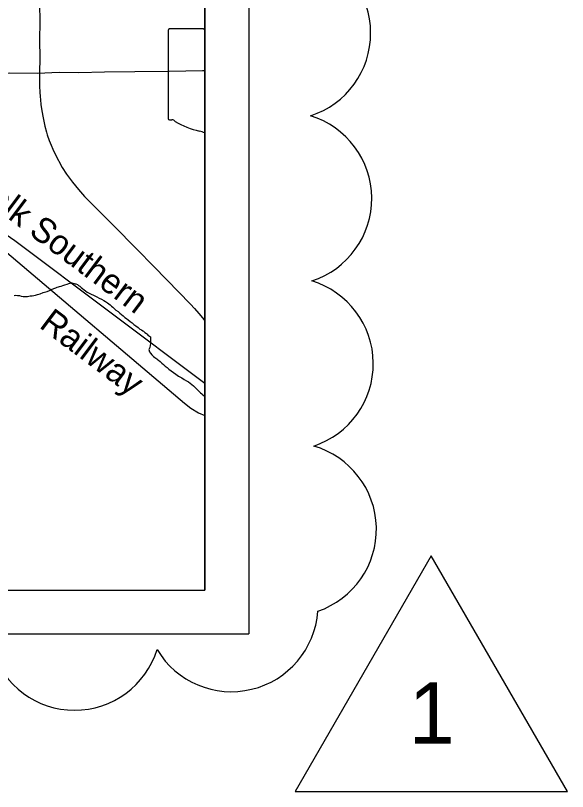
# Model space of a CAD drawing. Extents: x 0 to 96.2, y -27.5 to 31.3.
# Drawn here: x 50.194 to 51.448, y 13.529 to 15.293 of the extents above; entities that cross this region are included whole.
import ezdxf

# ---------------------------------------------------------------- set-up
doc = ezdxf.new("R2010")
doc.units = 0
for name, color, linetype in [('BOTTOM-BLKS', 7, 'Continuous'), ('TB1', 7, 'Continuous'), ('TB_BORDER', 7, 'Continuous'), ('TB_DUAL_PROF', 7, 'Continuous'), ('TB_PP_50x10_GRID', 7, 'Continuous'), ('TB_PROF_20x5', 7, 'Continuous'), ('TB_PSDSOD', 7, 'Continuous'), ('TB_SUPER_50x1_GRID', 7, 'Continuous')]:
    doc.layers.add(name, color=color, linetype=linetype)

msp = doc.modelspace()

# ---------------------------------------------------------------- linework, layer by layer
at = {"layer": 'BOTTOM-BLKS'}
msp.add_lwpolyline([(43.8234, 18.3711), (43.8234, 13.9869), (50.6234, 13.9869), (50.6234, 20.7869), (47.5697, 20.7869)], dxfattribs=at)
at = {"layer": 'TB1'}
for p, q in [((50.7234, 20.8869), (50.7234, 13.8869)), ((50.6234, 20.7869), (50.6234, 13.9869)), ((43.8234, 13.9869), (50.6234, 13.9869)), ((43.7234, 13.8869), (50.7234, 13.8869))]:
    msp.add_line(p, q, dxfattribs=at)
at = {"layer": 'TB_BORDER'}
for points in [[(50.1904, 14.6565), (50.1942, 14.6569), (50.1984, 14.6566), (50.203, 14.6563), (50.2068, 14.6552), (50.211, 14.6541), (50.2144, 14.6538), (50.2179, 14.6538), (50.2205, 14.6542), (50.2236, 14.6547), (50.227, 14.6555), (50.2311, 14.6559), (50.2349, 14.6564), (50.2387, 14.6568), (50.2437, 14.6584), (50.2497, 14.66), (50.2561, 14.6631), (50.2652, 14.6652), (50.2705, 14.6675), (50.2754, 14.6703), (50.2807, 14.6726), (50.2852, 14.6742), (50.2886, 14.675), (50.2913, 14.6758), (50.2939, 14.6766), (50.297, 14.6778), (50.3008, 14.679)], [(50.3008, 14.679), (50.3057, 14.6806), (50.311, 14.6822), (50.3147, 14.6838), (50.3174, 14.6846), (50.3212, 14.6854), (50.3288, 14.6829), (50.3307, 14.6829), (50.3346, 14.6814), (50.3369, 14.6795), (50.3396, 14.6773), (50.343, 14.6747), (50.3461, 14.6721), (50.3496, 14.6695), (50.3527, 14.6668), (50.3561, 14.6642), (50.3608, 14.6616), (50.3657, 14.6594), (50.3711, 14.6568), (50.378, 14.6531), (50.3838, 14.6506), (50.3891, 14.648), (50.3941, 14.645), (50.3983, 14.6424), (50.4026, 14.6398), (50.4056, 14.6376), (50.4087, 14.6349), (50.4118, 14.6323), (50.4145, 14.6297), (50.418, 14.6271), (50.4215, 14.623), (50.4265, 14.62), (50.4303, 14.6162), (50.4342, 14.6129), (50.4384, 14.6099), (50.4423, 14.6065), (50.4458, 14.6039), (50.4496, 14.6009), (50.4538, 14.5976), (50.4585, 14.5942), (50.4627, 14.5908), (50.4666, 14.5875), (50.472, 14.5834), (50.4762, 14.58), (50.4796, 14.5782), (50.4827, 14.5763), (50.4846, 14.5752), (50.4877, 14.5726), (50.4908, 14.5703), (50.4924, 14.5684), (50.4939, 14.5666), (50.4958, 14.5655), (50.5001, 14.5625), (50.5001, 14.5571), (50.5002, 14.5537), (50.5003, 14.5476), (50.4985, 14.5385), (50.4967, 14.5335), (50.498, 14.5286), (50.5003, 14.5252), (50.5034, 14.5214), (50.5069, 14.518), (50.5099, 14.5158), (50.5126, 14.514), (50.5146, 14.5128), (50.5165, 14.511), (50.5188, 14.5091), (50.5219, 14.5061), (50.5258, 14.5027), (50.53, 14.4994), (50.5339, 14.496), (50.5381, 14.493), (50.542, 14.4893), (50.5473, 14.4852), (50.5524, 14.4814), (50.5577, 14.4777), (50.5635, 14.4728), (50.5712, 14.4691), (50.5766, 14.4658), (50.5819, 14.4625), (50.5866, 14.4599), (50.5904, 14.4573), (50.5943, 14.4543), (50.5977, 14.4513), (50.607, 14.4419), (50.6097, 14.4389), (50.614, 14.4348), (50.6167, 14.4325), (50.6194, 14.4303), (50.6221, 14.428), (50.6234, 14.4271)], [(50.6234, 14.3358), (50.6232, 14.3348), (50.6229, 14.3329), (50.6233, 14.3276), (50.623, 14.3257), (50.6234, 14.3239)]]:
    msp.add_lwpolyline(points, dxfattribs=at)
at = {"layer": 'TB_DUAL_PROF'}
for p, q in [((50.5433, 15.2625), (50.5433, 15.2625)), ((50.6234, 15.0259), (50.6234, 15.2605)), ((50.5407, 15.0589), (50.5407, 15.0589))]:
    msp.add_line(p, q, dxfattribs=at)
for points in [[(50.5407, 15.2591), (50.5407, 15.2591), (50.5407, 15.0589)], [(50.6205, 15.2625), (50.6205, 15.2625), (50.5433, 15.2625)]]:
    msp.add_lwpolyline(points, dxfattribs=at)
for centre, radius, start, end in [((50.5437, 15.2595), 0.00305, 98.1301, 188.1301), ((50.6389, 15.2857), 0.0296, 231.6195, 238.3868), ((50.5437, 15.0585), 0.00308, 171.9584, 258.3066), ((50.5442, 15.079), 0.0235, 267.339, 280.6039), ((50.549, 15.0474), 0.00848, 29.7484, 93.2717), ((50.6561, 15.2272), 0.2019, 240.4129, 257.1985), ((50.5959, 14.969), 0.0632, 64.2129, 75.836)]:
    msp.add_arc(centre, radius, start, end, dxfattribs=at)
at = {"layer": 'TB_PP_50x10_GRID'}
for points in [[(50.2483, 15.32), (50.2485, 15.2779), (50.2484, 15.2382), (50.2485, 15.1953), (50.2482, 15.1639), (50.2484, 15.1323), (50.2488, 15.1188), (50.2494, 15.1091), (50.2502, 15.1009), (50.2514, 15.0908), (50.2528, 15.0807), (50.2555, 15.0644), (50.2605, 15.041), (50.2639, 15.0279), (50.2658, 15.0217), (50.2703, 15.0087), (50.2746, 14.9978), (50.2786, 14.9888), (50.2835, 14.9776), (50.2999, 14.9476), (50.3096, 14.932), (50.3228, 14.9137), (50.3364, 14.8971), (50.3504, 14.8817), (50.3724, 14.8594), (50.4151, 14.816), (50.4697, 14.7606), (50.5069, 14.7228), (50.5372, 14.6919), (50.5909, 14.6369), (50.6001, 14.6272), (50.6099, 14.6158), (50.6185, 14.6054), (50.6234, 14.5986)], [(49.5587, 15.2929), (49.5689, 15.2706), (49.5783, 15.2533), (49.595, 15.2277), (49.6207, 15.2011), (49.6542, 15.1695), (49.7154, 15.1177), (49.849, 15.0195), (50.1917, 14.7818), (50.6234, 14.4573)]]:
    msp.add_lwpolyline(points, dxfattribs=at)
at = {"layer": 'TB_PSDSOD'}
for points in [[(50.6234, 15.1671), (50.6187, 15.167), (50.5428, 15.1654), (50.465, 15.1645), (50.3955, 15.1638), (50.3378, 15.1629), (50.293, 15.1633), (50.2437, 15.1614), (50.18, 15.1615), (50.1025, 15.161), (50.0281, 15.161), (49.9541, 15.1605), (49.876, 15.1593), (49.8292, 15.159), (49.8042, 15.1589), (49.7462, 15.1571), (49.7049, 15.1611)], [(50.1684, 14.7584), (50.1737, 14.7543), (50.5777, 14.4118), (50.5916, 14.4004), (50.6096, 14.3899), (50.6234, 14.3837)]]:
    msp.add_lwpolyline(points, dxfattribs=at)
at = {"layer": 'TB_SUPER_50x1_GRID'}
msp.add_lwpolyline([(50.8287, 13.5289), (51.4475, 13.5289), (51.1381, 14.0648)], close=True, dxfattribs=at)
for centre, radius, start, end in [((50.8036, 15.2524), 0.1968, 287.7992, 72.7992), ((50.806, 14.8768), 0.1968, 287.9333, 72.9333), ((50.8096, 14.5011), 0.1968, 288.1756, 73.1756), ((50.8165, 14.1249), 0.1969, 288.9126, 73.9126), ((50.6841, 13.9525), 0.1967, 210.9707, 355.9707), ((50.3278, 13.9105), 0.1968, 197.5, 342.5)]:
    msp.add_arc(centre, radius, start, end, dxfattribs=at)

# ---------------------------------------------------------------- texts
at = {"layer": 'TB_PROF_20x5'}
for s, height, p in [('Norfolk Southern', 0.056629, (50.0129, 14.9538)), ('Railway', 0.05663, (50.2452, 14.5852))]:
    msp.add_text(s, height=height, rotation=323.0651, dxfattribs=at).set_placement(p)
at = {"layer": 'TB_SUPER_50x1_GRID'}
msp.add_text('1', height=0.14, dxfattribs=at).set_placement((51.0872, 13.6373))

doc.saveas('drawing.dxf')
